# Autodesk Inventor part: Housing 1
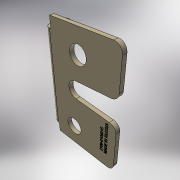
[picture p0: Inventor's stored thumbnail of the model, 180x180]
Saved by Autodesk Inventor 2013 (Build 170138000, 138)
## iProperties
Shininess: 64.0
Length Units: 11269
Angle Units: 11279
Time Units: 11290
Mass Units: 11283
Length Display Precision: 3
Angle Display Precision: 2
Compacted: True
Part Number: Housing 1
Document SubType Name: Листовой материал
Created: 2005-02
Material: Aluminum 6061
Designer: =<Author>
Manufacturer: Standard
Standards Organization: Custom
Density: 2.71 g/cm^3
Sheet Metal Rule: По умолчанию
Description: =<Part Number>
Mass: 32.3467 g
Surface Area: 94.081 cm^2
Volume: 11.9361 cm^3
Density: 0.0
Volumn: 0.0
Area: 0.0
PropertySet Name: Model Information
Control State: 0
Master: False
Checked Out: False
Checked Out Date: 2008-10-15
Last Check In Date: 2008-10-15
Толщина: 3.000 mm
Радиус_гибки: 2.000 mm
Ширина_просечки: 3.000 mm
Глубина_просечки: 1.500 mm
Размер_высечки: 12.000 mm
Минимальный_остаток: 6.000 mm
Радиус_перехода: 2.000 mm
JacobiRadiusSize: 3.000 mm
GapSize: 3.000 mm
d0: 53.000 mm
d1: 16.000 mm
d2: 79.000 mm
d3: 3.000 mm
d4: 1.500 mm
d5: 6.000 mm
d6: 2.000 mm
d7: 2.000 mm
d8: 0.500 mm
d9: 15.000 mm
d10: 27.000 mm
d11: 12.000 mm
d12: 50.000 mm
d13: 5.000 mm
d14: 12.000 mm
d15: 22.000 mm
d16: 2.000 mm
d17: 16.000 mm
d18: 2.000 mm
d19: 3.000 mm
d20: 0.00 deg
d21: 5.000 mm
d22: 65.000 mm
d23: 7.000 mm
d24: 6.000 mm
d25: 0.00 deg
d26: 20.000 mm
d27: 5.000 mm
d28: 29.500 mm
d38: 0.100 mm
Author: PVitaliy
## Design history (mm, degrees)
node "ФлнОтгиб1"
feature "Вырез1" dims "d19" = 3 (= Толщина), angle "d20" = 0 deg
feature "УглСкругление1" dims "d21" = 5
feature "Вырез2" dims "d24" = 6, angle "d25" = 0 deg
sketch "Эскиз4"
  geometry: L1 (-10.587, 4.909)-(-10.587, 49.109); L2 (-10.587, 49.109)-(-1.67, 49.109); L3 (-1.67, 49.109)-(-1.67, 4.909); L4 (-1.67, 4.909)-(-10.587, 4.909)
  constraints: 1 vertical, 2 other
feature "Рельеф1" sketch "Эскиз4" dims "d38" = 0.1, "d39" = 0, "Радиус_перехода" = 2 (= Радиус_гибки)
sketch "Эскиз1"
  geometry: L1 (0, 0)-(53, 0); L2 (0, 0)-(0, 16)
  constraints: 4 end point, 1 horizontal, 1 perpendicular, 1 other
  dimensions: "d0" = 53 distance of L1.start L1.end; "d1" = 16 distance of L1.start L2.end
feature "Пластина1" dims "d2" = 79, "d3" = 3 (= Ширина_просечки), "d5" = 6 (= Минимальный_остаток), "d7" = 2 (= Радиус_гибки), "d8" = 0.5, "Толщина" = 3
feature "Изгиб1" dims "d3" = 3 (= Ширина_просечки), "d4" = 1.5 (= Глубина_просечки), "d5" = 6 (= Минимальный_остаток), "d6" = 2 (= Радиус_гибки), "d7" = 2 (= Радиус_гибки), "d8" = 0.5, "Толщина" = 3, "Зазор_стыка" = 0.01
sketch "Эскиз2"
  geometry: L1 (0, 79)-(0, 0) reference; L2 (-48, 79)-(0, 79) reference; L3 (0, 50.014)-(-29.413, 47.986); L4 (0, 34.014)-(-29.407, 36.014); C1 r 6 at (-27, 64); C2 r 6 at (-32, 14); A1 r 6 centre (-29, 42) between (-29.413, 47.986) and (-29.407, 36.014)
  constraints: 4 end point, 3 centre point, 2 point on circle, 2 point on line, 2 tangent, 1 equal radius
  dimensions: "d9" = 15 distance from line of C1.centre L2; "d10" = 27 distance from line of C1.centre L1; "d11" = 12 diameter of C1; "d12" = 50 vertical distance of C2.centre C1.centre; "d13" = 5 horizontal distance of C2.centre C1.centre; "d14" = 12 diameter of A1; "d15" = 22 vertical distance of A1.centre C1.centre; "d16" = 2 horizontal distance of A1.centre C1.centre; "d17" = 16 distance of L4.start L3.start; "d18" = 2 vertical distance of L4.start L4.end
sketch "Эскиз3"
  geometry: L1 (79, 0)-(79, -11) reference; L2 (79, 0)-(0, 0) reference; L3 (0, 0)-(0, -11) reference; L4 (0, -13)-(79, -13) reference; L5 (79, -16)-(0, -16) reference; L6 (0, -11)-(0, -16) reference; L7 (79, -11)-(79, -16) reference; L8 (7, 0)-(7, -16); L9 (72, 0)-(72, -16); L10 (0, -11)-(79, -11) reference; L11 (29.5, -13)-(29.5, -5); L12 (29.5, -5)-(49.5, -5); L13 (49.5, -5)-(49.5, -13)
  constraints: 10 end point, 6 point on line, 4 perpendicular, 1 parallel
  dimensions: "d22" = 65 distance between parallel lines of L8 L9; "d23" = 7 distance between parallel lines of L8 L3; "d26" = 20 distance of L11.end L12.end; "d27" = 5 distance between parallel lines of L12 L2; "d28" = 29.5 distance between parallel lines of L11 L3
other parameters: "Радиус_гибки" = 2, "Ширина_просечки" = 3 (= Толщина), "Глубина_просечки" = 1.5 (= 0.5 x Толщина), "Размер_высечки" = 12 (= 4 x Толщина), "Минимальный_остаток" = 6 (= 2 x Толщина), "JacobiRadiusSize" = 3 (= Толщина), "GapSize" = 3 (= Толщина)
